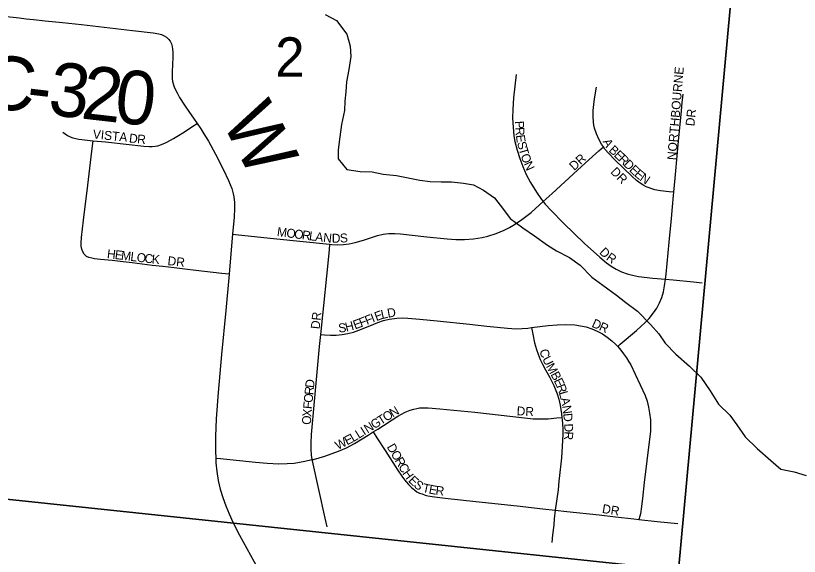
# Model space of a CAD drawing. Extents: x 1410790 to 1770854, y 566777 to 831614.
# Drawn here: x 1593644 to 1598025, y 687834 to 690858 of the extents above; entities that cross this region are included whole.
import ezdxf

# ---------------------------------------------------------------- set-up
doc = ezdxf.new("R2010")
doc.units = 0
for name, color, linetype in [('GM_X_County_Road', 7, 'Continuous'), ('GM_X_County_Road_Text', 7, 'Continuous'), ('GM_X_Minor_River', 7, 'Continuous'), ('GM_X_Section', 7, 'Continuous'), ('GM_X_Section_Text', 7, 'Continuous'), ('GM_X_Township_Subdivision', 7, 'Continuous'), ('GM_X_Township_Subdivision_Text', 7, 'Continuous')]:
    doc.layers.add(name, color=color, linetype=linetype)

msp = doc.modelspace()

# ---------------------------------------------------------------- linework, layer by layer
at = {"layer": 'GM_X_County_Road'}
for points in [[(1593578, 690854.5), (1593663.6, 690845.3), (1593702.5, 690841.1), (1593742.4, 690836.8), (1593808.3, 690829.7), (1593906, 690819.1), (1594010.9, 690807.7), (1594296.5, 690775.2), (1594411.9, 690761.9), (1594443.8, 690756.7), (1594459, 690752.2), (1594473.3, 690745.9), (1594486.2, 690737.4), (1594497.5, 690726.8), (1594506.9, 690714.4), (1594513.9, 690700.5), (1594518.7, 690685.7), (1594521.2, 690670.1), (1594521.8, 690654.2), (1594521.7, 690621.9), (1594519.7, 690589.2), (1594517.9, 690539.7), (1594519, 690506.5), (1594521, 690489.8), (1594525.3, 690471.9), (1594531.7, 690454.2), (1594545.9, 690425.8), (1594560.1, 690401), (1594588.2, 690358), (1594616, 690316.9), (1594638.1, 690284.7), (1594657.8, 690254.3)], [(1594657.8, 690254.3), (1594679.3, 690224), (1594696, 690196.6), (1594720.9, 690155.1), (1594760.3, 690083.4), (1594805.3, 689995.9), (1594833.2, 689936.8), (1594851.3, 689891.4), (1594860.3, 689860.4), (1594863.4, 689844.6), (1594867, 689812.6), (1594867.4, 689780.1), (1594864.5, 689731.2), (1594856.3, 689635.3)], [(1594856.3, 689635.3), (1594839.4, 689436.9), (1594837, 689411.5)], [(1594837, 689411.5), (1594818.3, 689208.1), (1594794.1, 688963.2), (1594775.4, 688750.5), (1594765.5, 688603.3), (1594761.3, 688504.8), (1594761.1, 688422.6), (1594762.5, 688383.1)], [(1594762.5, 688383.1), (1594763.4, 688356.7), (1594768.2, 688307.4), (1594776.2, 688258.5), (1594787.4, 688210.2), (1594801.8, 688162.8), (1594818.5, 688116.3), (1594836.8, 688070.5), (1594857.1, 688025.5), (1594894.8, 687952.4), (1594997.6, 687765.4)]]:
    msp.add_lwpolyline(points, dxfattribs=at)
at = {"layer": 'GM_X_Minor_River'}
msp.add_lwpolyline([(1595373.8, 690864.3), (1595437.4, 690831.8), (1595494.8, 690755.3), (1595514.2, 690687), (1595517.8, 690629), (1595507.3, 690557), (1595492.8, 690487), (1595490.4, 690431), (1595484, 690379), (1595481.6, 690327), (1595465, 690249), (1595456.5, 690181), (1595446, 690107), (1595447.6, 690057), (1595495.1, 689996.6), (1595568.9, 689986), (1595636.8, 689983.5), (1595698.6, 689971), (1595772.5, 689964.4), (1595828.3, 689952), (1595904.1, 689937.4), (1595962, 689931), (1596021.9, 689928.5), (1596079.8, 689928.1), (1596147.7, 689921.6), (1596203.5, 689911.1), (1596259.2, 689882.7), (1596320.8, 689838.2), (1596370.3, 689773.8), (1596407.8, 689723.4), (1596479.3, 689670.8), (1596544.9, 689626.3), (1596616.4, 689573.7), (1596668.1, 689543.3), (1596739.8, 689504.7), (1596799.4, 689462.2), (1596864.8, 689395.7), (1596926.4, 689351.1), (1597003.8, 689294.5), (1597055.5, 689254.1), (1597121, 689205.5), (1597192.3, 689130.9), (1597239.9, 689078.5), (1597275.4, 689026.2), (1597334.9, 688963.7), (1597410.3, 688897), (1597473.8, 688836.5), (1597527.1, 688760), (1597572.5, 688685.6), (1597635.9, 688623), (1597675.5, 688568.7), (1597722.9, 688502.2), (1597790.3, 688437.7), (1597865.7, 688369), (1597921.3, 688320.5), (1597997.1, 688305.9), (1598062.8, 688285.4)], dxfattribs=at)
at = {"layer": 'GM_X_Section'}
for points in [[(1592523.5, 693611.4), (1597838.4, 693072.3), (1597349.3, 687756.6), (1592038.7, 688317.6)], [(1597838.4, 693072.3), (1603189.9, 692572.7), (1602694.7, 687247), (1597349.3, 687756.6)], [(1597349.3, 687756.6), (1596853.3, 682490.5), (1591841.6, 682980.9), (1591574.1, 683010.7), (1592038.7, 688317.6)]]:
    msp.add_lwpolyline(points, close=True, dxfattribs=at)
at = {"layer": 'GM_X_Township_Subdivision'}
for points in [[(1596442.7, 690528), (1596427.6, 690398), (1596422.5, 690332.7), (1596422, 690283.7), (1596424.6, 690234.6), (1596429.7, 690185.8), (1596435.5, 690153.7), (1596447.7, 690106.5), (1596462.1, 690059.6), (1596478.8, 690013.4), (1596498.7, 689968.6), (1596522.2, 689925.5), (1596556.6, 689869.8), (1596584.5, 689829.5), (1596593.6, 689817.8)], [(1596929.5, 690123.9), (1596919.3, 690138.4), (1596903.4, 690167.5), (1596890.3, 690197.8), (1596880.3, 690229.4), (1596876.7, 690245.5), (1596874.3, 690261.8), (1596872.4, 690294.8), (1596873.2, 690327.9), (1596875.7, 690360.8), (1596879.8, 690393.3), (1596890.3, 690458.6)], [(1597323.8, 689869.9), (1597330.7, 689949.6), (1597344.6, 690095), (1597352, 690176.1), (1597363.8, 690306), (1597371.1, 690370.9), (1597376.4, 690419.3)], [(1594077.5, 690158.3), (1594145, 690151.9), (1594278.6, 690137), (1594343, 690130), (1594359.2, 690128.6), (1594389.6, 690125.3), (1594406.7, 690125.9), (1594423.2, 690127.9), (1594439, 690130.4), (1594459.2, 690136.7), (1594485.8, 690148.1), (1594509.8, 690161.3), (1594526.2, 690170.8), (1594545.2, 690182.9), (1594586.9, 690208.2), (1594633.7, 690239.8), (1594657.8, 690254.3)], [(1593906.8, 690207.2), (1593919.8, 690196.7), (1593933.6, 690187.2), (1593948.4, 690179.5), (1593964, 690173.9), (1593980.2, 690170), (1593996.7, 690167.3), (1594077.5, 690158.3)], [(1594837, 689411.5), (1594795.8, 689416.1), (1594650.5, 689432.2), (1594588.6, 689439.9), (1594529, 689447), (1594465.8, 689454.8), (1594406.9, 689461.2), (1594294, 689475.3), (1594228.7, 689482.5), (1594182.6, 689488.1), (1594117.6, 689494.1), (1594085.2, 689498.4), (1594069.1, 689500.8), (1594053.2, 689504.4), (1594038.7, 689511.7), (1594027, 689523.1), (1594018.4, 689536.9), (1594012.9, 689552.2), (1594010.1, 689568.3), (1594009.4, 689584.6), (1594011.8, 689617.2), (1594022.9, 689714.6), (1594047, 689910.6), (1594069.7, 690100.8), (1594077.5, 690158.3)], [(1596593.6, 689817.8), (1596643.5, 689864.1), (1596785.6, 689994.6), (1596868.9, 690070.5), (1596905.1, 690102.5), (1596929.5, 690123.9)], [(1597323.8, 689869.9), (1597298.3, 689872.6), (1597249.1, 689877.7), (1597216.5, 689884), (1597200.6, 689888.7), (1597185, 689894.3), (1597169.7, 689900.8), (1597155, 689908.2), (1597140.8, 689916.7), (1597114.6, 689936.8), (1597089.9, 689958.9), (1596994.4, 690050.7), (1596959.6, 690086.1), (1596938.3, 690111.3), (1596929.5, 690123.9)], [(1597276.9, 689383.8), (1597280.7, 689411.4), (1597296.9, 689591.8), (1597309.7, 689722.9), (1597316.3, 689788.1), (1597322.3, 689852.9), (1597323.8, 689869.9)], [(1595398.7, 689579.7), (1595411.3, 689578.4), (1595444, 689576.6), (1595476.6, 689577.4), (1595508.4, 689581.1), (1595541, 689588.5), (1595588, 689602.4), (1595665.9, 689627.4), (1595697.7, 689635.2), (1595713.8, 689637.9), (1595730.1, 689639.7), (1595762.8, 689640.3), (1595795.5, 689638.3), (1595941.9, 689621.5), (1596055.7, 689608.7), (1596104.7, 689605.8), (1596153.8, 689606.4), (1596202.8, 689610.5), (1596251.3, 689617.8), (1596283.2, 689625.3), (1596329.9, 689640.3), (1596375.5, 689658.6), (1596405, 689672.8), (1596433.4, 689689), (1596473.8, 689716.9), (1596525, 689757.8), (1596593.6, 689817.8)], [(1596593.6, 689817.8), (1596604.6, 689803.7), (1596637.4, 689767.4), (1596706.7, 689697.8), (1596824.5, 689584.3), (1596909, 689506.9), (1596947, 689475.8), (1596973.7, 689456.9), (1597001.8, 689440), (1597031.1, 689425.5), (1597061.9, 689414.3), (1597093.4, 689405.6), (1597125.5, 689399.3), (1597206.6, 689390.2), (1597276.9, 689383.8)], [(1594856.3, 689635.3), (1594890.1, 689631.7), (1595085.5, 689610.9), (1595398.7, 689579.7)], [(1595398.7, 689579.7), (1595395.8, 689548), (1595380.9, 689399.9), (1595364.9, 689236.6), (1595347.9, 689074.6)], [(1597011.2, 689007.6), (1597023.4, 689020.6), (1597114.5, 689097.2), (1597162.8, 689142.4), (1597185.7, 689164.5), (1597210.8, 689195.3), (1597229.1, 689222.6), (1597244.4, 689251.6), (1597256.5, 689282.3), (1597265.6, 689313.9), (1597271.8, 689346.2), (1597276.9, 689383.8)], [(1597276.9, 689383.8), (1597320.5, 689379.7), (1597433.9, 689369.5), (1597482.6, 689363.8)], [(1595347.9, 689074.6), (1595370.2, 689073.2), (1595403, 689071.2), (1595435.8, 689071.4), (1595468.6, 689074.3), (1595500.8, 689080), (1595532.4, 689088), (1595562.9, 689097.9), (1595623, 689122.8), (1595668.3, 689142.1), (1595699.8, 689152.4), (1595731.4, 689159.7), (1595761.4, 689164.5), (1595774.8, 689165.7), (1595805.2, 689166.8), (1595837.2, 689165.8), (1595902.8, 689160.6), (1596001, 689150.9), (1596180.7, 689132.3), (1596278.6, 689121.5), (1596392.9, 689109.5), (1596442.1, 689107), (1596474.9, 689107.7), (1596507.6, 689110.5), (1596527.5, 689113.1)], [(1596527.5, 689113.1), (1596621.6, 689125.4), (1596670.7, 689129), (1596720, 689129.9), (1596769.2, 689127.9), (1596801.8, 689123.8), (1596833.9, 689116.8), (1596865.1, 689106.7), (1596895.3, 689093.6), (1596924.1, 689078), (1596951.4, 689059.7), (1596976.7, 689038.8), (1596998.9, 689019.1), (1597011.2, 689007.6)], [(1596527.5, 689113.1), (1596534.5, 689076.5), (1596544.2, 689027.9), (1596554.9, 688991.3), (1596564.8, 688964.7), (1596577, 688934.3), (1596588.9, 688908.6), (1596606.3, 688876.5), (1596630.8, 688833.8), (1596652.4, 688789.3), (1596671.1, 688743.5), (1596680.8, 688712), (1596687.8, 688679.8), (1596695.1, 688630.9), (1596697.3, 688610.9)], [(1595347.9, 689074.6), (1595340.8, 689007.4), (1595317.6, 688761.5), (1595302.5, 688597), (1595296.4, 688515.1), (1595293.6, 688466.1), (1595293.5, 688433.2), (1595295.9, 688400.4), (1595300.4, 688374.4)], [(1597011.2, 689007.6), (1597026.5, 688987.7), (1597042.4, 688965.6), (1597058.2, 688944), (1597072.4, 688921.9), (1597082.4, 688904.3), (1597107.6, 688851.8), (1597136.3, 688792.7), (1597162.8, 688732.5), (1597174.1, 688701.7), (1597182.1, 688668.3), (1597188.1, 688634.5), (1597192.7, 688596.9), (1597193.4, 688566.9), (1597192.7, 688531.6), (1597187.4, 688489.5), (1597158.1, 688246.8), (1597149, 688158), (1597141.6, 688099.2), (1597139, 688085), (1597136.5, 688071.5), (1597133.3, 688058.6), (1597128.7, 688040.2)], [(1595643.1, 688529.3), (1595669.2, 688545.8), (1595699.5, 688565.1), (1595748.4, 688596.3), (1595781.2, 688617.3), (1595821.6, 688640.1), (1595848.5, 688651.8), (1595869.7, 688657), (1595885.7, 688660.9), (1595901.8, 688663.4), (1595918.1, 688664.9), (1595950.8, 688665), (1596016.1, 688659.1), (1596211.6, 688639.4), (1596423.2, 688615.1), (1596537.1, 688602.9), (1596582.6, 688602.2), (1596621.4, 688603), (1596670.2, 688608.1), (1596697.3, 688610.9)], [(1596697.3, 688610.9), (1596698.8, 688598.1), (1596702.4, 688548.8), (1596703, 688515.8), (1596697.7, 688416.9), (1596695, 688384), (1596693.4, 688367.7), (1596684.7, 688286.3), (1596681.2, 688253.8), (1596676, 688205.3), (1596660.7, 688092.7)], [(1595300.4, 688374.4), (1595308.8, 688376.2), (1595371.8, 688394.1), (1595449, 688421.4), (1595493.9, 688441.1), (1595537.4, 688464.1), (1595614.5, 688511.3), (1595643.1, 688529.3)], [(1595643.1, 688529.3), (1595663.7, 688496.9), (1595709.6, 688426.3), (1595778.3, 688316.8), (1595806.2, 688276), (1595826.3, 688251), (1595839.9, 688235.2), (1595856.3, 688219.5), (1595875.6, 688203.1), (1595887.1, 688195.2), (1595901.4, 688187.3), (1595915.7, 688182.3), (1595932.9, 688176.6), (1595948.6, 688172.3), (1595985.1, 688166.6), (1596045.2, 688158.7), (1596216.9, 688140.8), (1596447.2, 688116.5), (1596591.8, 688100), (1596660.7, 688092.7)], [(1594762.5, 688383.1), (1594788.4, 688380.7), (1594804.8, 688379.3), (1594983.9, 688359.7), (1595049.2, 688354), (1595114.6, 688351.3), (1595162.4, 688352.1), (1595201.1, 688355.5), (1595260.8, 688365.8), (1595300.4, 688374.4)], [(1595300.4, 688374.4), (1595301.5, 688367.9), (1595373, 688046.4), (1595383.7, 687998.2)], [(1596660.7, 688092.7), (1596655.4, 688042.8), (1596651.8, 688007.1), (1596646.1, 687953.4), (1596641.4, 687910.7)], [(1596660.7, 688092.7), (1596725.5, 688085), (1596906.5, 688065.7), (1596998.1, 688055), (1597100.6, 688043.4), (1597128.7, 688040.2)], [(1597128.7, 688040.2), (1597231, 688028.7), (1597345.2, 688016.4)]]:
    msp.add_lwpolyline(points, dxfattribs=at)

# ---------------------------------------------------------------- texts
at = {"layer": 'GM_X_County_Road_Text'}
for s, rotation, p in [('C', 353.2913, (1593451.3, 690348.4)), ('3', 353.3432, (1593818.7, 690305.2)), ('2', 353.4658, (1594002.9, 690283.7)), ('0', 353.8878, (1594188.9, 690262.4)), ('-', 353.3006, (1593696.1, 690319.6)), ('W', 297.3396, (1594791, 690272.1))]:
    msp.add_text(s, height=300, rotation=rotation, dxfattribs=at).set_placement(p)
at = {"layer": 'GM_X_Section_Text'}
msp.add_text('2', height=221, rotation=0, dxfattribs=at).set_placement((1595094.7, 690515.9))
at = {"layer": 'GM_X_Township_Subdivision_Text'}
for s, rotation, p in [('NORTHBOURNE', 85.1899, (1597335.9, 690048.3)), ('DR', 83.994, (1597438.2, 690237.7)), ('P', 273.1707, (1596435.1, 690268)), ('R', 273.1879, (1596437.1, 690232.9)), ('VISTA', 354.4288, (1594073.1, 690171.3)), ('D', 353.241, (1594275.4, 690149.3)), ('R', 355.4816, (1594321.2, 690143.9)), ('E', 278.3573, (1596439.8, 690188.4)), ('S', 285.6834, (1596446.3, 690146.8)), ('A', 298.3052, (1596923.8, 690154)), ('T', 286.2382, (1596456, 690112.4)), ('B', 317.9267, (1596956.1, 690100.6)), ('E', 315.9854, (1596985.2, 690074.4)), ('O', 288.5803, (1596466.5, 690076.5)), ('DR', 42.8801, (1596766.9, 689988.4)), ('R', 315.979, (1597010.5, 690049.9)), ('D', 315.9815, (1597039, 690022.4)), ('N', 294.5282, (1596482.6, 690029.5)), ('DR', 315, (1596966.2, 689980.9)), ('E', 316.1475, (1597070.7, 689991.7)), ('E', 319.6013, (1597098.6, 689965.1)), ('N', 325.2101, (1597129.6, 689939.1)), ('M', 352.7123, (1595102.5, 689625.7)), ('O', 352.723, (1595154.9, 689619)), ('O', 352.7123, (1595198.6, 689613.4)), ('R', 352.7183, (1595242.2, 689607.8)), ('L', 352.7123, (1595281.5, 689602.8)), ('A', 352.723, (1595316.4, 689598.4)), ('N', 353.7626, (1595361, 689592.7)), ('D', 0.8261, (1595411.5, 689587.6)), ('S', 3.3359, (1595457.9, 689588.3)), ('H', 353.1325, (1594152.1, 689502.5)), ('E', 353.1258, (1594195.8, 689497.2)), ('M', 353.1268, (1594230.7, 689493)), ('L', 353.1274, (1594283.1, 689486.7)), ('O', 353.1306, (1594318.1, 689482.5)), ('C', 353.3694, (1594362, 689477.2)), ('K', 354.7503, (1594402.6, 689472.5)), ('D', 316.7081, (1596903.5, 689530.3)), ('R', 324.8645, (1596941.4, 689495.3)), ('DR', 353.988, (1594490.9, 689462.9)), ('D', 10.1055, (1595725.5, 689168.1)), ('DR', 83.9826, (1595342.8, 689102.6)), ('F', 21.4548, (1595574.7, 689115.1)), ('F', 21.4548, (1595607.4, 689128)), ('I', 21.4577, (1595640.2, 689140.8)), ('E', 20.1372, (1595660.4, 689148.8)), ('L', 12.797, (1595691.8, 689160.4)), ('S', 6.7354, (1595450.5, 689084.7)), ('H', 13.6626, (1595491.9, 689090)), ('E', 20.7973, (1595541.2, 689102.4)), ('D', 335.7035, (1596860.7, 689119)), ('R', 336.2578, (1596901.2, 689100.7)), ('C', 286.9795, (1596571.3, 688984.9)), ('U', 296.7336, (1596586.4, 688938.4)), ('M', 299.3277, (1596607.3, 688896.9)), ('B', 297.9282, (1596633, 688851.1)), ('D', 84.5058, (1595311.4, 688774)), ('E', 295.0804, (1596651.3, 688816.7)), ('R', 84.5274, (1595307.7, 688734.6)), ('R', 291.2197, (1596665.8, 688785.7)), ('O', 84.5249, (1595303.5, 688690.7)), ('L', 286.1968, (1596679.8, 688749.9)), ('F', 84.5001, (1595300.1, 688655.7)), ('A', 282.9389, (1596689.4, 688716.8)), ('X', 84.9006, (1595296.2, 688612)), ('O', 31.9923, (1595714.9, 688585.8)), ('N', 31.0462, (1595752, 688609)), ('DR', 356.9833, (1596443.8, 688622.6)), ('N', 277.8272, (1596699.1, 688675.1)), ('O', 87.5513, (1595294.3, 688568.6)), ('G', 31.9984, (1595647.7, 688543.9)), ('T', 31.9735, (1595685, 688567.2)), ('D', 275.6486, (1596705, 688632)), ('I', 31.9806, (1595591.7, 688508.9)), ('N', 31.9923, (1595610.4, 688520.5)), ('D', 271.3554, (1596710.3, 688576)), ('E', 27.3327, (1595496.4, 688454)), ('L', 30.6914, (1595530.5, 688471.7)), ('L', 31.9228, (1595561.8, 688490.2)), ('R', 268.1297, (1596711.3, 688532.8)), ('W', 26.6478, (1595444.7, 688428)), ('D', 300.3115, (1595716.8, 688446.1)), ('O', 300.3115, (1595739, 688408.1)), ('R', 300.2932, (1595761.2, 688370.2)), ('C', 300.3283, (1595781.2, 688335.9)), ('H', 305.2942, (1595803.7, 688297.8)), ('E', 315.6689, (1595835.6, 688254.4)), ('S', 321.6903, (1595865, 688226)), ('T', 347.6248, (1595914.8, 688193.7)), ('E', 349.3441, (1595950.8, 688185.8)), ('R', 353.4215, (1595989.2, 688178.7)), ('DR', 350.5377, (1596920.1, 688076.8))]:
    msp.add_text(s, height=50, rotation=rotation, dxfattribs=at).set_placement(p)

doc.saveas('drawing.dxf')
